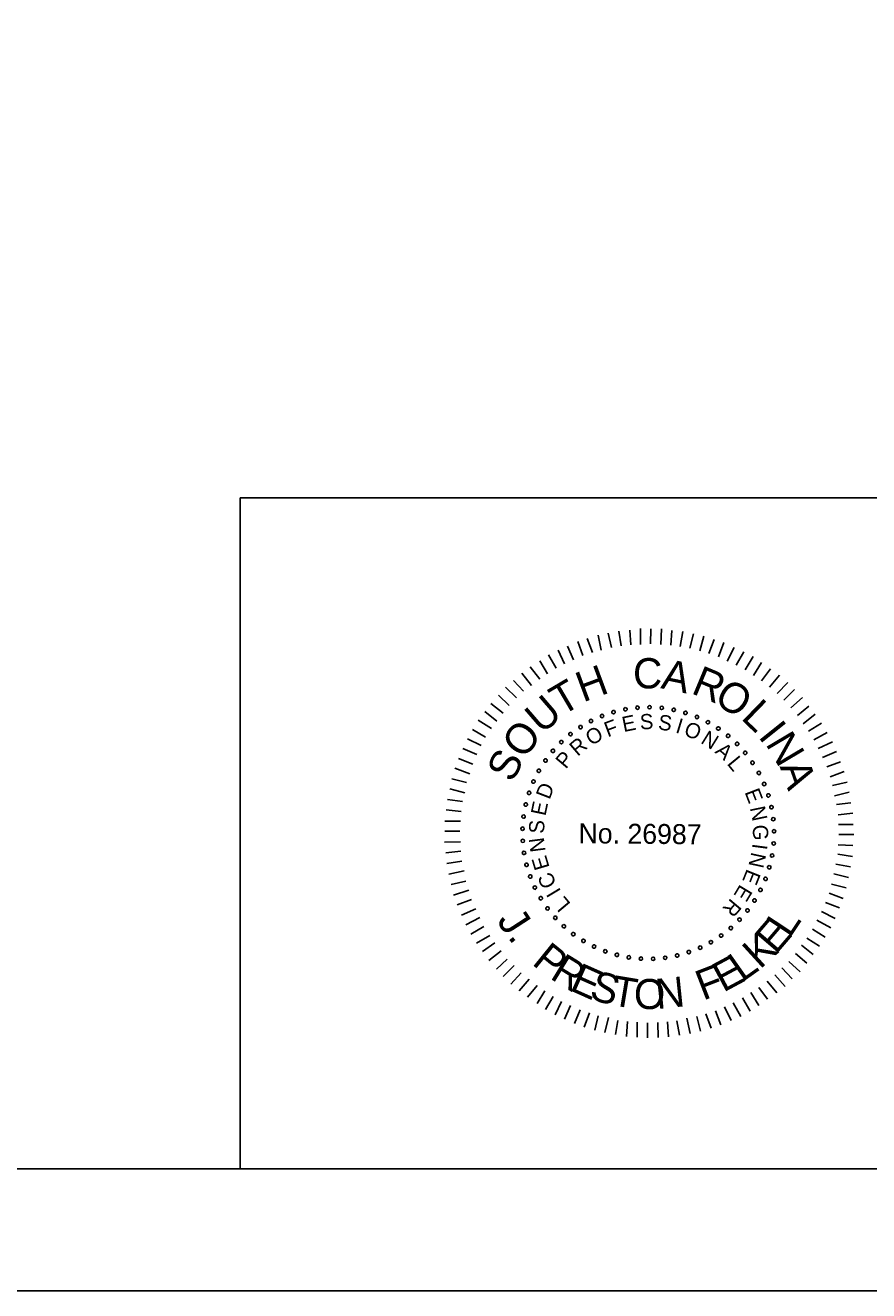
# Model space of a CAD drawing. Extents: x -121.2 to -24.9, y 6.4 to 66.6.
# Drawn here: x -63.15 to -53.93, y 6.35 to 20.18 of the extents above; entities that cross this region are included whole.
import ezdxf

# ---------------------------------------------------------------- set-up
doc = ezdxf.new("R2010")
doc.units = 0
for name, color, linetype in [('BR_BORDER LINES', 7, 'Continuous'), ('BR_TEXT', 7, 'Continuous'), ('Level 31', 7, 'Continuous')]:
    doc.layers.add(name, color=color, linetype=linetype)

msp = doc.modelspace()

# ---------------------------------------------------------------- linework, layer by layer
at = {"layer": 'BR_BORDER LINES'}
for p, q in [((-60.804, 15.017), (-46.496, 15.017)), ((-60.804, 7.683), (-60.804, 15.017)), ((-116.272, 7.683), (-26.496, 7.683))]:
    msp.add_line(p, q, dxfattribs=at)
at = {"layer": 'BR_TEXT'}
for p, q in [((-56.639, 13.398), (-56.663, 13.561)), ((-56.534, 13.409), (-56.544, 13.572)), ((-56.428, 13.415), (-56.427, 13.587)), ((-56.316, 13.421), (-56.315, 13.586)), ((-56.204, 13.413), (-56.198, 13.585)), ((-56.097, 13.405), (-56.084, 13.568)), ((-55.994, 13.393), (-55.965, 13.555)), ((-57.056, 13.292), (-57.112, 13.448)), ((-56.951, 13.326), (-57.009, 13.479)), ((-56.855, 13.352), (-56.89, 13.515)), ((-56.744, 13.379), (-56.782, 13.537)), ((-55.886, 13.372), (-55.848, 13.529)), ((-55.777, 13.343), (-55.734, 13.505)), ((-55.679, 13.315), (-55.62, 13.468)), ((-55.574, 13.28), (-55.515, 13.435)), ((-57.35, 13.155), (-57.432, 13.3)), ((-57.258, 13.202), (-57.328, 13.352)), ((-57.16, 13.247), (-57.223, 13.396)), ((-55.478, 13.233), (-55.403, 13.381)), ((-55.382, 13.187), (-55.298, 13.335)), ((-55.282, 13.138), (-55.196, 13.281)), ((-57.528, 13.035), (-57.632, 13.171)), ((-57.445, 13.092), (-57.526, 13.236)), ((-55.193, 13.073), (-55.103, 13.216)), ((-55.104, 13.015), (-55.007, 13.149)), ((-57.705, 12.902), (-57.816, 13.021)), ((-57.617, 12.967), (-57.724, 13.101)), ((-55.018, 12.946), (-54.909, 13.078)), ((-57.783, 12.829), (-57.901, 12.947)), ((-54.934, 12.879), (-54.818, 12.997)), ((-54.859, 12.805), (-54.743, 12.921)), ((-57.929, 12.663), (-58.061, 12.767)), ((-57.862, 12.747), (-57.978, 12.86)), ((-54.784, 12.722), (-54.657, 12.833)), ((-54.712, 12.636), (-54.587, 12.738)), ((-57.998, 12.574), (-58.13, 12.681)), ((-54.648, 12.547), (-54.517, 12.651)), ((-58.121, 12.399), (-58.264, 12.485)), ((-58.056, 12.497), (-58.2, 12.585)), ((-54.589, 12.468), (-54.449, 12.554)), ((-54.531, 12.37), (-54.388, 12.453)), ((-58.168, 12.308), (-58.318, 12.382)), ((-54.483, 12.278), (-54.329, 12.35)), ((-58.214, 12.21), (-58.367, 12.278)), ((-54.436, 12.179), (-54.284, 12.244)), ((-58.294, 12), (-58.458, 12.061)), ((-58.261, 12.107), (-58.416, 12.166)), ((-54.391, 12.075), (-54.24, 12.131)), ((-58.327, 11.904), (-58.489, 11.945)), ((-54.355, 11.968), (-54.202, 12.026)), ((-54.329, 11.871), (-54.168, 11.909)), ((-58.346, 11.792), (-58.512, 11.835)), ((-54.307, 11.759), (-54.146, 11.799)), ((-58.374, 11.696), (-58.536, 11.718)), ((-54.285, 11.663), (-54.127, 11.682)), ((-58.394, 11.481), (-58.566, 11.483)), ((-58.386, 11.587), (-58.551, 11.606)), ((-54.267, 11.553), (-54.105, 11.57)), ((-58.4, 11.372), (-58.567, 11.373)), ((-54.264, 11.447), (-54.103, 11.446)), ((-58.396, 11.257), (-58.568, 11.254)), ((-54.266, 11.223), (-54.105, 11.217)), ((-54.258, 11.338), (-54.095, 11.336)), ((-58.39, 11.154), (-58.555, 11.135)), ((-54.271, 11.12), (-54.109, 11.098)), ((-58.379, 11.044), (-58.542, 11.02)), ((-58.353, 10.939), (-58.52, 10.904)), ((-54.29, 11.011), (-54.132, 10.984)), ((-58.335, 10.826), (-58.498, 10.789)), ((-54.338, 10.793), (-54.178, 10.753)), ((-54.314, 10.905), (-54.154, 10.867)), ((-58.304, 10.728), (-58.469, 10.672)), ((-54.366, 10.695), (-54.213, 10.637)), ((-58.273, 10.625), (-58.429, 10.569)), ((-58.228, 10.526), (-58.382, 10.454)), ((-54.403, 10.593), (-54.253, 10.534)), ((-58.183, 10.429), (-58.335, 10.35)), ((-54.499, 10.399), (-54.346, 10.318)), ((-54.45, 10.495), (-54.3, 10.42)), ((-58.138, 10.331), (-58.283, 10.247)), ((-54.548, 10.301), (-54.407, 10.215)), ((-58.075, 10.232), (-58.22, 10.148)), ((-58.018, 10.153), (-58.152, 10.056)), ((-54.668, 10.126), (-54.539, 10.026)), ((-54.608, 10.203), (-54.469, 10.117)), ((-57.95, 10.064), (-58.084, 9.959)), ((-57.885, 9.974), (-58.002, 9.865)), ((-54.733, 10.037), (-54.61, 9.931)), ((-57.808, 9.904), (-57.927, 9.784)), ((-57.73, 9.824), (-57.844, 9.701)), ((-54.883, 9.88), (-54.77, 9.758)), ((-54.807, 9.948), (-54.682, 9.837)), ((-57.644, 9.754), (-57.753, 9.629)), ((-57.555, 9.685), (-57.662, 9.558)), ((-55.044, 9.733), (-54.938, 9.606)), ((-54.959, 9.801), (-54.846, 9.676)), ((-57.473, 9.627), (-57.557, 9.488)), ((-57.38, 9.567), (-57.464, 9.423)), ((-55.311, 9.55), (-55.228, 9.405)), ((-55.222, 9.608), (-55.134, 9.468)), ((-55.132, 9.665), (-55.037, 9.536)), ((-57.289, 9.513), (-57.361, 9.365)), ((-57.191, 9.467), (-57.256, 9.319)), ((-57.088, 9.42), (-57.147, 9.27)), ((-55.606, 9.408), (-55.55, 9.256)), ((-55.509, 9.453), (-55.437, 9.304)), ((-55.413, 9.498), (-55.331, 9.348)), ((-56.983, 9.387), (-57.044, 9.232)), ((-56.888, 9.354), (-56.925, 9.197)), ((-56.778, 9.335), (-56.818, 9.171)), ((-56.673, 9.305), (-56.699, 9.149)), ((-56.568, 9.292), (-56.58, 9.128)), ((-56.462, 9.285), (-56.464, 9.12)), ((-56.35, 9.277), (-56.352, 9.114)), ((-56.238, 9.283), (-56.235, 9.118)), ((-56.131, 9.289), (-56.121, 9.124)), ((-56.028, 9.299), (-56.001, 9.143)), ((-55.92, 9.328), (-55.884, 9.163)), ((-55.81, 9.346), (-55.77, 9.187)), ((-55.711, 9.377), (-55.655, 9.221))]:
    msp.add_line(p, q, dxfattribs=at)
for centre, start, end in [((-56.46, 12.723), 5.0653, 185.0653), ((-56.328, 12.728), 359.5268, 179.5268), ((-56.328, 12.728), 179.5268, 359.5268), ((-56.195, 12.72), 353.9884, 173.9884), ((-56.968, 12.577), 27.2191, 207.2191), ((-56.847, 12.632), 21.6807, 201.6807), ((-56.847, 12.632), 201.6807, 21.6807), ((-56.721, 12.674), 16.1422, 196.1422), ((-56.721, 12.674), 196.1422, 16.1422), ((-56.592, 12.705), 10.6038, 190.6038), ((-56.592, 12.705), 190.6038, 10.6038), ((-56.46, 12.723), 185.0653, 5.0653), ((-56.195, 12.72), 173.9884, 353.9884), ((-56.064, 12.699), 348.4499, 168.4499), ((-56.064, 12.699), 168.4499, 348.4499), ((-55.935, 12.666), 162.9114, 342.9114), ((-55.935, 12.666), 342.9114, 162.9114), ((-55.81, 12.621), 157.373, 337.373), ((-55.81, 12.621), 337.373, 157.373), ((-57.192, 12.434), 38.2961, 218.2961), ((-57.083, 12.511), 32.7576, 212.7576), ((-57.083, 12.511), 212.7576, 32.7576), ((-56.968, 12.577), 207.2191, 27.2191), ((-55.69, 12.564), 151.8345, 331.8345), ((-55.69, 12.564), 331.8345, 151.8345), ((-55.576, 12.495), 146.2961, 326.2961), ((-55.576, 12.495), 326.2961, 146.2961), ((-57.292, 12.347), 43.8345, 223.8345), ((-57.292, 12.347), 223.8345, 43.8345), ((-57.192, 12.434), 218.2961, 38.2961), ((-55.47, 12.416), 140.7576, 320.7576), ((-55.47, 12.416), 320.7576, 140.7576), ((-55.371, 12.327), 135.2191, 315.2191), ((-55.371, 12.327), 315.2191, 135.2191), ((-57.384, 12.25), 49.373, 229.373), ((-57.384, 12.25), 229.373, 49.373), ((-55.282, 12.229), 129.6807, 309.6807), ((-55.282, 12.229), 309.6807, 129.6807), ((-57.537, 12.033), 60.4499, 240.4499), ((-57.537, 12.033), 240.4499, 60.4499), ((-57.465, 12.145), 54.9114, 234.9114), ((-57.465, 12.145), 234.9114, 54.9114), ((-55.202, 12.122), 124.1422, 304.1422), ((-55.202, 12.122), 304.1422, 124.1422), ((-57.597, 11.915), 65.9884, 245.9884), ((-57.597, 11.915), 245.9884, 65.9884), ((-55.133, 12.009), 118.6038, 298.6038), ((-55.133, 12.009), 298.6038, 118.6038), ((-55.075, 11.889), 113.0653, 293.0653), ((-55.075, 11.889), 293.0653, 113.0653), ((-57.645, 11.791), 71.5268, 251.5268), ((-57.645, 11.791), 251.5268, 71.5268), ((-55.029, 11.764), 107.5268, 287.5268), ((-55.029, 11.764), 287.5268, 107.5268), ((-57.681, 11.663), 77.0653, 257.0653), ((-57.681, 11.663), 257.0653, 77.0653), ((-54.996, 11.636), 101.9884, 281.9884), ((-54.996, 11.636), 281.9884, 101.9884), ((-57.705, 11.532), 82.6038, 262.6038), ((-57.705, 11.532), 262.6038, 82.6038), ((-54.975, 11.504), 96.4499, 276.4499), ((-54.975, 11.504), 276.4499, 96.4499), ((-57.716, 11.4), 88.1422, 268.1422), ((-57.716, 11.4), 268.1422, 88.1422), ((-54.967, 11.372), 90.9114, 270.9114), ((-54.967, 11.372), 270.9114, 90.9114), ((-57.714, 11.267), 93.6807, 273.6807), ((-57.714, 11.267), 273.6807, 93.6807), ((-54.971, 11.239), 85.373, 265.373), ((-54.971, 11.239), 265.373, 85.373), ((-57.7, 11.135), 99.2191, 279.2191), ((-57.7, 11.135), 279.2191, 99.2191), ((-54.989, 11.107), 79.8345, 259.8345), ((-54.989, 11.107), 259.8345, 79.8345), ((-57.672, 11.005), 104.7576, 284.7576), ((-57.672, 11.005), 284.7576, 104.7576), ((-55.019, 10.978), 74.2961, 254.2961), ((-55.019, 10.978), 254.2961, 74.2961), ((-57.632, 10.878), 110.2961, 290.2961), ((-57.632, 10.878), 290.2961, 110.2961), ((-55.061, 10.852), 68.7576, 248.7576), ((-55.061, 10.852), 248.7576, 68.7576), ((-57.581, 10.756), 115.8345, 295.8345), ((-57.581, 10.756), 295.8345, 115.8345), ((-57.517, 10.639), 121.373, 301.373), ((-57.517, 10.639), 301.373, 121.373), ((-55.115, 10.731), 63.2191, 243.2191), ((-55.115, 10.731), 243.2191, 63.2191), ((-57.443, 10.529), 126.9114, 306.9114), ((-57.443, 10.529), 306.9114, 126.9114), ((-55.258, 10.507), 52.1422, 232.1422), ((-55.258, 10.507), 232.1422, 52.1422), ((-55.181, 10.615), 57.6807, 237.6807), ((-55.181, 10.615), 237.6807, 57.6807), ((-57.358, 10.426), 132.4499, 312.4499), ((-57.358, 10.426), 312.4499, 132.4499), ((-55.344, 10.406), 46.6038, 226.6038), ((-55.344, 10.406), 226.6038, 46.6038), ((-57.264, 10.333), 137.9884, 317.9884), ((-57.264, 10.333), 317.9884, 137.9884), ((-57.161, 10.248), 143.5268, 323.5268), ((-57.161, 10.248), 323.5268, 143.5268), ((-55.545, 10.232), 35.5268, 215.5268), ((-55.545, 10.232), 215.5268, 35.5268), ((-55.44, 10.314), 41.0653, 221.0653), ((-55.44, 10.314), 221.0653, 41.0653), ((-57.051, 10.174), 149.0653, 329.0653), ((-57.051, 10.174), 329.0653, 149.0653), ((-56.934, 10.112), 154.6038, 334.6038), ((-56.934, 10.112), 334.6038, 154.6038), ((-55.775, 10.1), 24.4499, 204.4499), ((-55.775, 10.1), 204.4499, 24.4499), ((-55.657, 10.16), 29.9884, 209.9884), ((-55.657, 10.16), 209.9884, 29.9884), ((-56.811, 10.06), 160.1422, 340.1422), ((-56.811, 10.06), 340.1422, 160.1422), ((-56.684, 10.021), 345.6807, 165.6807), ((-56.684, 10.021), 165.6807, 345.6807), ((-56.554, 9.994), 351.2191, 171.2191), ((-56.554, 9.994), 171.2191, 351.2191), ((-56.422, 9.98), 356.7576, 176.7576), ((-56.422, 9.98), 176.7576, 356.7576), ((-56.289, 9.978), 2.2961, 182.2961), ((-56.289, 9.978), 182.2961, 2.2961), ((-56.157, 9.99), 7.8345, 187.8345), ((-56.157, 9.99), 187.8345, 7.8345), ((-56.026, 10.014), 13.373, 193.373), ((-56.026, 10.014), 193.373, 13.373), ((-55.899, 10.051), 18.9114, 198.9114), ((-55.899, 10.051), 198.9114, 18.9114)]:
    msp.add_arc(centre, 0.0187, start, end, dxfattribs=at)
at = {"layer": 'Level 31'}
msp.add_lwpolyline([(-121.161, 6.35), (-25.161, 6.35), (-25.161, 65.017), (-121.161, 65.017)], close=True, dxfattribs=at)

# ---------------------------------------------------------------- texts
at = {"layer": 'BR_TEXT'}
for s, height, rotation, p in [('H', 0.331, 20.3637, (-57.055, 12.779)), ('C', 0.331, 359.5482, (-56.51, 12.935)), ('A', 0.331, 348.1981, (-56.213, 12.937)), ('R', 0.331, 337.4344, (-55.884, 12.884)), ('T', 0.331, 30.4992, (-57.29, 12.626)), ('O', 0.33, 326.5869, (-55.638, 12.786)), ('U', 0.331, 40.8022, (-57.506, 12.426)), ('L', 0.331, 315.9488, (-55.338, 12.605)), ('F', 0.166, 20.6127, (-56.785, 12.398)), ('E', 0.166, 11.4103, (-56.611, 12.456)), ('S', 0.166, 2.208, (-56.431, 12.485)), ('S', 0.166, 352.6608, (-56.241, 12.485)), ('I', 0.166, 343.1136, (-56.053, 12.453)), ('O', 0.331, 52.0267, (-57.705, 12.149)), ('O', 0.166, 30.8477, (-56.965, 12.302)), ('O', 0.166, 338.4392, (-55.964, 12.426)), ('N', 0.166, 328.2042, (-55.778, 12.342)), ('I', 0.331, 308.6613, (-55.148, 12.407)), ('N', 0.331, 300.7037, (-55.066, 12.329)), ('R', 0.166, 40.3949, (-57.115, 12.185)), ('A', 0.166, 318.657, (-55.621, 12.235)), ('S', 0.33, 63.2511, (-57.826, 11.894)), ('P', 0.166, 49.9421, (-57.243, 12.045)), ('L', 0.166, 309.4546, (-55.488, 12.109)), ('A', 0.331, 289.4792, (-54.908, 12.081)), ('D', 0.166, 69.0364, (-57.421, 11.711)), ('E', 0.166, 291.049, (-55.291, 11.801)), ('E', 0.166, 78.2388, (-57.466, 11.533)), ('N', 0.166, 281.8466, (-55.232, 11.628)), ('S', 0.166, 87.786, (-57.481, 11.344)), ('No. 26987', 0.218, 359.5268, (-57.105, 11.241)), ('G', 0.166, 272.2995, (-55.201, 11.441)), ('N', 0.166, 97.3332, (-57.464, 11.154)), ('I', 0.166, 262.4084, (-55.202, 11.244)), ('E', 0.166, 106.5355, (-57.419, 10.977)), ('N', 0.166, 257.7339, (-55.214, 11.151)), ('E', 0.166, 248.1867, (-55.262, 10.968)), ('C', 0.166, 116.4266, (-57.339, 10.797)), ('I', 0.166, 121.1011, (-57.291, 10.717)), ('L', 0.166, 129.9595, (-57.183, 10.578)), ('E', 0.166, 238.9844, (-55.337, 10.8)), ('R', 0.166, 229.782, (-55.437, 10.647)), ('J', 0.329, 302.9559, (-58.004, 10.395)), ('E', 0.329, 49.3639, (-54.948, 10.017)), ('L', 0.329, 56.4247, (-54.795, 10.198)), ('K', 0.329, 42.3031, (-55.122, 9.857)), ('.', 0.329, 309.3974, (-57.886, 10.214)), ('P', 0.329, 321.1035, (-57.624, 9.923)), ('R', 0.329, 328.5359, (-57.428, 9.768)), ('E', 0.329, 28.1814, (-55.523, 9.606)), ('L', 0.329, 35.2422, (-55.315, 9.719)), ('E', 0.329, 335.9684, (-57.215, 9.64)), ('S', 0.329, 343.0292, (-56.998, 9.545)), ('F', 0.329, 21.1206, (-55.743, 9.519)), ('T', 0.329, 350.4617, (-56.759, 9.474)), ('O', 0.329, 358.1419, (-56.504, 9.434)), ('N', 0.329, 5.8221, (-56.247, 9.428))]:
    msp.add_text(s, height=height, rotation=rotation, dxfattribs=at).set_placement(p)

doc.saveas('drawing.dxf')
